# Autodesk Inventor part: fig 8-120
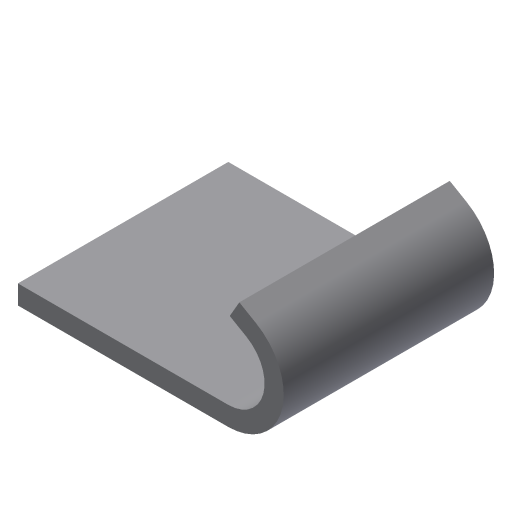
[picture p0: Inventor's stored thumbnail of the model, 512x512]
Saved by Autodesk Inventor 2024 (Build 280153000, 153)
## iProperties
Created: 2009-09
Part Number: fig 8-120
Document SubType Name: Modeling
Designer: Sham
Density: 1 g/cm^3
Material: Generic
Appearance: Default
Author: Sham
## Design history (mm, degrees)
sketch "Sketch1"
  geometry: L1 (-33.976, 22)-(0, 22); L2 (0, 22)-(0, 0); L3 (0, 0)-(-33.976, 0); L4 (-33.976, 0)-(-33.976, 22)
  constraints: 8 end point, 2 parallel, 1 horizontal, 1 perpendicular
extrude "Extrusion1" new body sketch "Sketch1" distance "d0" = 2; taper "d1" = 0 deg
sketch "Sketch2"
  geometry: L1 (-12, 22)-(-12, 0)
  constraints: 2 end point
feature "Bend Part1" sketch "Sketch2" dims "d4" = 10, "d5" = 150 deg
body "Solid1"
